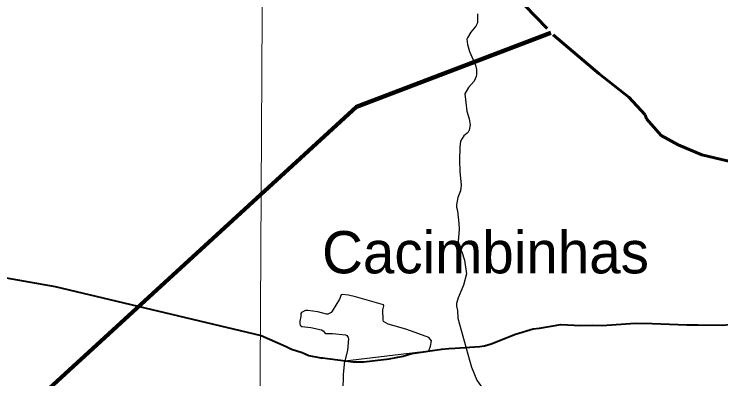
# Model space of a CAD drawing. Extents: x 553962 to 842807, y 8883888 to 9032388.
# Drawn here: x 716710 to 725065, y 8959644 to 8963960 of the extents above; entities that cross this region are included whole.
import ezdxf

# ---------------------------------------------------------------- set-up
doc = ezdxf.new("R2010")
doc.units = 0
doc.header["$LTSCALE"] = 200
doc.linetypes.add('LONG_DASH_SHORT_DASH', pattern=[9.9, 6, -1.2, 1.5, -1.2])
for name, color, linetype, lineweight in [('1', 7, 'Continuous', 13), ('12', 7, 'Continuous', 25), ('21', 7, 'Continuous', 25), ('24', 7, 'Continuous', 25), ('7', 7, 'Continuous', 90), ('9', 7, 'Continuous', 90)]:
    doc.layers.add(name, color=color, linetype=linetype, lineweight=lineweight)
doc.layers.add('41', color=7, linetype='Continuous')

msp = doc.modelspace()

# ---------------------------------------------------------------- linework, layer by layer
at = {"layer": '1'}
msp.add_lwpolyline([(719978.9, 9023574.5), (719561.6, 8949232.2), (719215.6, 8890710.6)], dxfattribs=at)
at = {"layer": '12', "lineweight": 40}
for points in [[(710551.5, 8961397.1), (711177.1, 8961501.2), (712016, 8961727.1), (712359, 8961724.2), (713550.7, 8961508.2), (716056.5, 8960938), (717193.5, 8960736.2), (719630.3, 8960157.3)], [(721922.9, 8960009), (722213.7, 8960025.4), (722269.8, 8960036.4), (722349.1, 8960058.4), (722636.1, 8960173.1), (722845.7, 8960234.4), (722922.5, 8960243.5), (723174, 8960287.2), (723408.1, 8960273.8), (723541.7, 8960277.9), (723662.4, 8960276.1), (724053.4, 8960301.3), (724251.5, 8960299.1), (724661.8, 8960282.6), (724797.4, 8960284.4), (725081.1, 8960280.5), (725171.8, 8960288.1), (725504.3, 8960282.4), (725962.1, 8960286.2), (726091.1, 8960280.3), (726144.9, 8960281.9)], [(719630.3, 8960157.3), (719924.9, 8960025), (719991.1, 8959995.2), (720116.1, 8959954.9), (720192.2, 8959919.6), (720337.5, 8959893.8), (720356.6, 8959891.3)], [(721309.9, 8959913.9), (721410.9, 8959945.9), (721766.8, 8959996.8), (721847.5, 8960004.7), (721922.9, 8960009)], [(720356.6, 8959891.3), (720717.1, 8959843.9), (720842.5, 8959844.2), (721142.7, 8959881.7), (721309.9, 8959913.9)]]:
    msp.add_lwpolyline(points, dxfattribs=at)
at = {"layer": '12'}
msp.add_lwpolyline([(720615.2, 8959855.5), (720600.9, 8959695.2), (720597, 8959505.1), (720630.5, 8959292.2), (720652.8, 8959055), (720632.1, 8958659.5), (720635, 8958462), (720656.1, 8958337.2), (720700.8, 8958191.8), (720743.2, 8958010.9), (720791.1, 8957885.8), (720852.6, 8957752.9), (720877.2, 8957688.2), (720888, 8957623.8), (720908.9, 8957434.4), (720919.8, 8957236.9), (720915.8, 8956822.8), (720917.5, 8956475.5), (720890.2, 8956243.7), (720885.8, 8956166.3), (720886.8, 8956088.9), (720868.9, 8955947.1), (720826.5, 8955484.8)], dxfattribs=at)
at = {"layer": '21'}
for points in [[(721081.2, 8960508.1), (721077.4, 8960519.1), (720747.7, 8960615.2), (720662.9, 8960634.1), (720587.2, 8960643), (720575.8, 8960636.9), (720556, 8960586.9), (720470.6, 8960443.6), (720458.9, 8960430), (720418.1, 8960410.7), (720402.2, 8960408.3), (720301.9, 8960437.2), (720181, 8960453.2), (720156.1, 8960451.2), (720109.1, 8960428.1), (720098.9, 8960418.5), (720097.9, 8960382.4), (720087.7, 8960324.8), (720086.7, 8960296.8), (720091.3, 8960280.8), (720111.5, 8960263.6), (720216.2, 8960251.9), (720344.2, 8960222.5), (720362.4, 8960214), (720382.8, 8960188), (720394.4, 8960180.7), (720474.7, 8960182.3), (720628.9, 8960163.3), (720641.9, 8960157.8), (720658.4, 8960133.9), (720662.8, 8960119.5), (720650.8, 8959977.9), (720618.4, 8959856.9), (721612.4, 8959974.7)], [(721612.4, 8959974.7), (721632.5, 8960032.7), (721644.1, 8960093.2), (721614, 8960131.4), (721452.9, 8960193.9), (721340.2, 8960231.7), (721132.5, 8960290.7), (721078, 8960323.4), (721072, 8960337.7), (721069.2, 8960462.3), (721081.2, 8960508.1)]]:
    msp.add_lwpolyline(points, dxfattribs=at)
at = {"layer": '24'}
for points in [[(722187, 8963962.1), (722189.1, 8963859.1), (722167.7, 8963817.5), (722110.5, 8963747.7), (722070.3, 8963681.7), (722063.8, 8963664.4), (722068.1, 8963601.1), (722094, 8963516.1), (722162.6, 8963358.1), (722176.2, 8963303.1), (722177, 8963244), (722173.6, 8963223), (722150.4, 8963167.1), (722082.2, 8963092.3), (722039.2, 8963018), (722060.5, 8962810.2), (722090.5, 8962720.7), (722103.1, 8962648.5), (722089.6, 8962588.8), (722078.8, 8962562.8), (722066.8, 8962550.6), (722025.2, 8962521.8), (721986.8, 8962458), (721978, 8962385), (721975.3, 8962231.7), (721979, 8962096), (721995.3, 8961934.2), (721985.8, 8961870.2), (721954.4, 8961789.1)], [(721954.4, 8961789.1), (721939, 8961701.5), (721940.5, 8961675.6), (721951.9, 8961632), (721968.9, 8961483.5), (721970.5, 8961415.5), (721961.3, 8961271), (721974.8, 8961199.1), (722002.5, 8961147.9), (722036.1, 8961049.7), (722059, 8960887.1), (722022.2, 8960752.4), (721958.8, 8960603.3), (721941.3, 8960535.4), (721939.8, 8960504.4), (721952, 8960451.2), (721953.6, 8960363.9)], [(721953.6, 8960363.9), (722093.6, 8959865.1), (722115.4, 8959783), (722181.9, 8959629.9), (722261.1, 8959510.9)]]:
    msp.add_lwpolyline(points, dxfattribs=at)
at = {"layer": '7', "linetype": 'LONG_DASH_SHORT_DASH', "lineweight": 60}
msp.add_lwpolyline([(722178.5, 8964657), (723083.4, 8963715.2), (723625.8, 8963254.3), (723977.8, 8962977.1), (724168.2, 8962768.7), (724186.8, 8962722.9), (724359.5, 8962523.2), (724559.4, 8962414.2), (724841.1, 8962296.1), (725141, 8962223.5), (725386.8, 8962222.5), (725788.6, 8962283.2), (726090.3, 8962454.2), (726984.4, 8963189.7), (727272.9, 8963654), (727265.1, 8963720.5), (727171.4, 8963825.9), (727177.2, 8963835.7), (727083.5, 8963916.6), (726881.4, 8964145.8)], dxfattribs=at)
at = {"layer": '9'}
msp.add_lwpolyline([(705081.2, 8958366.8), (705509.2, 8948874.2), (720755.9, 8962863.6), (723053.6, 8963740.6)], dxfattribs=at)

# ---------------------------------------------------------------- texts
at = {"layer": '41'}
msp.add_text('Cacimbinhas', height=500, dxfattribs=at).set_placement((720350.3, 8960892.5))

doc.saveas('drawing.dxf')
